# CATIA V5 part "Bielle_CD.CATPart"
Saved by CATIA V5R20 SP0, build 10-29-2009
Part number: Bielle_CD
Bounding box of the stored display mesh (mm): x -4 to 7, y -6.037 to 42.147, z 55.288 to 79.13
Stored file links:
  D:\Dropbox\IAO_2012\IAO_2012_753_jrecappe\jrecappe.zip\Bielle_CD.CATPart
  D:\Dropbox\IAO_2012\IAO_2012_753_jrecappe\jrecappe.zip\Ass_brevetIAO_skl.CATProduct
  D:\Dropbox\IAO_2012\IAO_2012_753_jrecappe\jrecappe.zip\Ass_skl_levier2bras.CATProduct
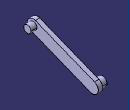
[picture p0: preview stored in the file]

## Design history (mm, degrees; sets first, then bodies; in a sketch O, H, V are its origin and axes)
Set1
  DatumPoint1 "Point C": linked copy from another document
  DatumPoint2 "Point D": linked copy from another document
Body1 (main body)
  Sketch1 on yz-plane, origin (0, 0, 0), H (0, 1, 0), V (0, 0, 1)
    construction line L1 (38.1498, 59.2861) -> (-2.039, 75.1322)
    point P1 (38.1498, 59.2861)
    point P2 (-2.039, 75.1322)
    line L2 (36.6826, 55.5649) -> (-3.5062, 71.411)
    line L3 (-0.5717, 78.8534) -> (39.6171, 63.0073)
    arc A1 centre (-2.039, 75.1322) radius 4 from (-3.5062, 71.411) to (-0.5717, 78.8534) cw
    arc A2 centre (38.1498, 59.2861) radius 4 from (39.6171, 63.0073) to (36.6826, 55.5649) cw
    reference projected point E1 (-2.039, 75.1322) from DatumPoint1
    reference projected point E2 (38.1498, 59.2861) from DatumPoint2
    distance L1 L2 = 4
    tangency: A1 L2, A2 L2, A1 L3, A2 L3
    coincidence: P2 E1, P1 E2
  Pad1: profile Sketch1, direction (1, 0, 0), length 3
  Sketch2 on yz-plane, origin (0, 0, 0), H (0, 1, 0), V (0, 0, 1)
    circle A1 centre (38.1498, 59.2861) radius 3
    point P1 (38.1498, 59.2861)
    reference projected point E1 (38.1498, 59.2861) from DatumPoint2
    coincidence: P1 E1
  Pad2: profile Sketch2, direction (1, 0, 0), length -4
  Sketch3 on yz-plane, origin (0, 0, 0), H (0, 1, 0), V (0, 0, 1)
    circle A1 centre (-2.039, 75.1322) radius 2.5
    point P1 (-2.039, 75.1322)
    reference projected point E1 (-2.039, 75.1322) from DatumPoint1
    coincidence: P1 E1
  Pad3: profile Sketch3, direction (1, 0, 0), length 7, opposite side length -3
